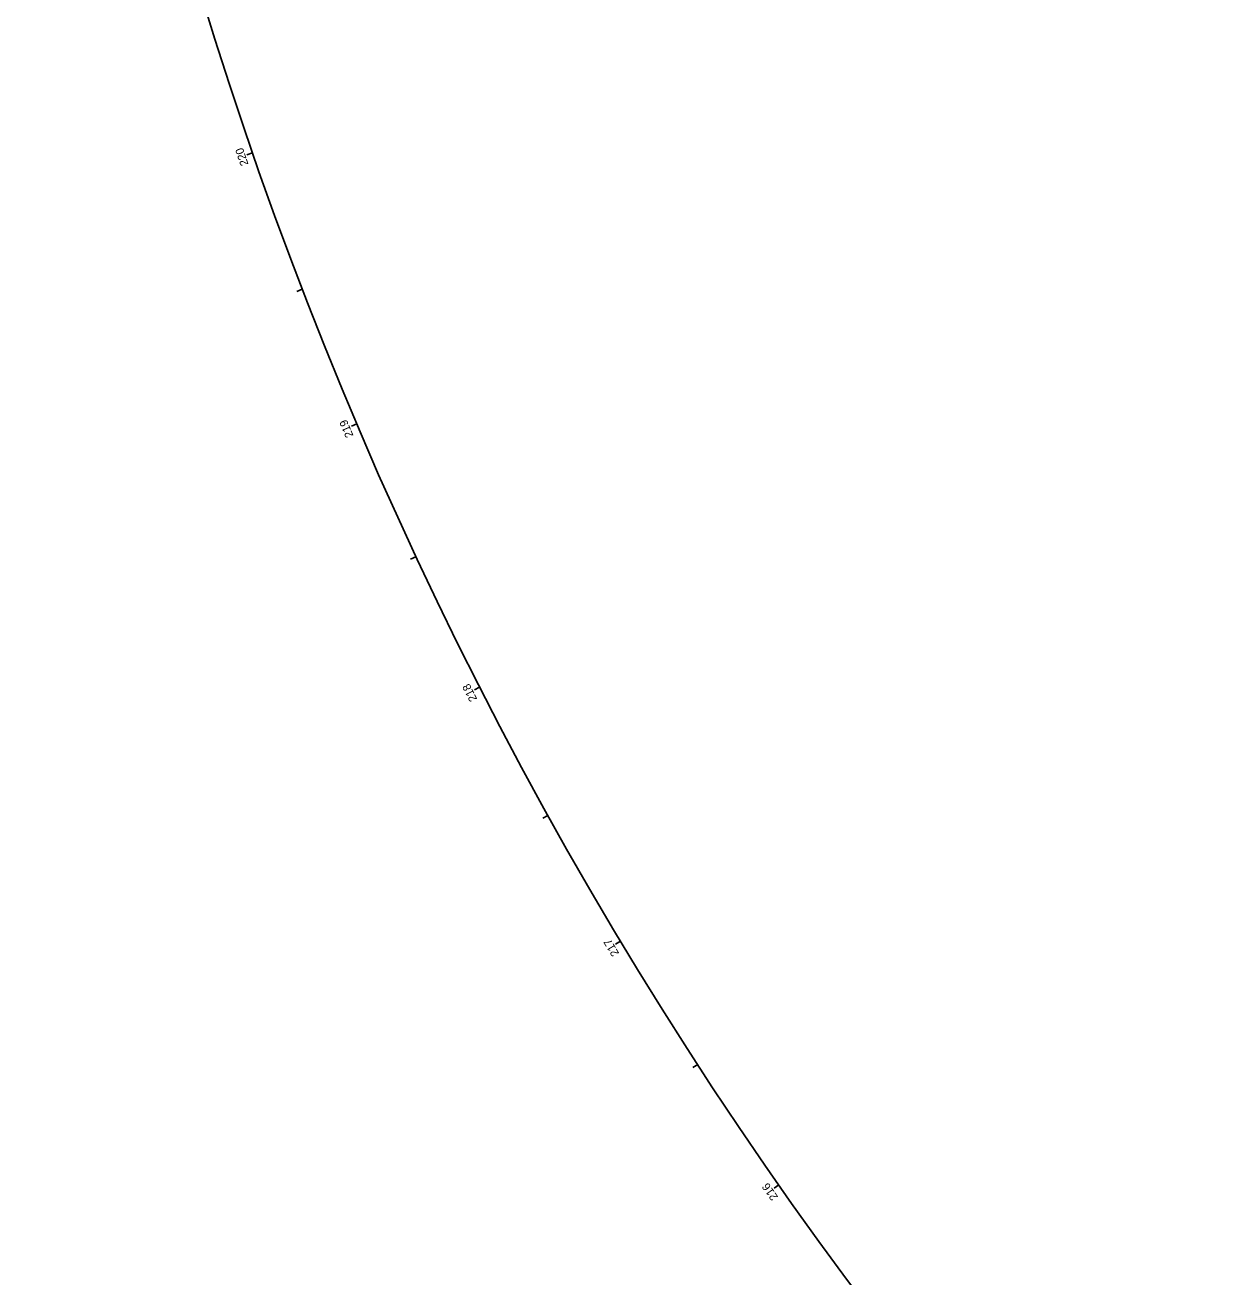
# Model space of a CAD drawing. Extents: x 1454426 to 1455277, y 587472 to 590476.
# Drawn here: x 1454431 to 1454844.3, y 587916.7 to 588347.4 of the extents above; entities that cross this region are included whole.
import ezdxf

# ---------------------------------------------------------------- set-up
doc = ezdxf.new("R2010")
doc.units = 0
for name, color, linetype in [('Default', 7, 'Continuous'), ('GT_Target_Soil_Boring', 7, 'Continuous'), ('PV_P_Saw_Cut_Line', 7, 'Continuous'), ('SC_Scratch1', 7, 'Continuous'), ('SC_Scratch2', 7, 'Continuous'), ('SC_Scratch3', 7, 'Continuous')]:
    doc.layers.add(name, color=color, linetype=linetype)

msp = doc.modelspace()

# ---------------------------------------------------------------- linework, layer by layer
at = {"layer": 'Default'}
for centre in [(1454509.27, 588303.48), (1454509.27, 588303.48), (1454509.27, 588303.48), (1454545.15, 588210.16), (1454545.15, 588210.16), (1454545.15, 588210.16), (1454587.45, 588119.57), (1454587.45, 588119.57), (1454587.45, 588119.57), (1454635.96, 588032.15), (1454635.96, 588032.15), (1454635.96, 588032.15), (1454690.46, 587948.33), (1454690.46, 587948.33), (1454690.46, 587948.33)]:
    msp.add_circle(centre, 0.0000833, dxfattribs=at)
at = {"layer": 'GT_Target_Soil_Boring'}
msp.add_arc((1455863.38, 588770.51), 1432.39, 161.3175, 244.97965, dxfattribs=at)
at = {"layer": 'PV_P_Saw_Cut_Line'}
msp.add_arc((1455863.38, 588770.51), 1432.39, 161.3175, 244.97965, dxfattribs=at)
at = {"layer": 'SC_Scratch1'}
for p, q in [((1454509.27, 588303.48), (1454507.38, 588302.83)), ((1454526.39, 588256.51), (1454524.53, 588255.79)), ((1454545.15, 588210.16), (1454543.31, 588209.38)), ((1454565.51, 588164.5), (1454563.69, 588163.65)), ((1454587.45, 588119.57), (1454585.66, 588118.66)), ((1454610.94, 588075.44), (1454609.19, 588074.47)), ((1454635.96, 588032.15), (1454634.25, 588031.12)), ((1454662.48, 587989.77), (1454660.8, 587988.68)), ((1454690.46, 587948.33), (1454688.82, 587947.18))]:
    msp.add_line(p, q, dxfattribs=at)
at = {"layer": 'SC_Scratch2'}
for p, q in [((1454509.27, 588303.48), (1454507.38, 588302.83)), ((1454526.39, 588256.51), (1454524.53, 588255.79)), ((1454545.15, 588210.16), (1454543.31, 588209.38)), ((1454565.51, 588164.5), (1454563.69, 588163.65)), ((1454587.45, 588119.57), (1454585.66, 588118.66)), ((1454610.94, 588075.44), (1454609.19, 588074.47)), ((1454635.96, 588032.15), (1454634.25, 588031.12)), ((1454662.48, 587989.77), (1454660.8, 587988.68)), ((1454690.46, 587948.33), (1454688.82, 587947.18))]:
    msp.add_line(p, q, dxfattribs=at)
at = {"layer": 'SC_Scratch3'}
for p, q in [((1454509.27, 588303.48), (1454507.38, 588302.83)), ((1454526.39, 588256.51), (1454524.53, 588255.79)), ((1454545.15, 588210.16), (1454543.31, 588209.38)), ((1454565.51, 588164.5), (1454563.69, 588163.65)), ((1454587.45, 588119.57), (1454585.66, 588118.66)), ((1454610.94, 588075.44), (1454609.19, 588074.47)), ((1454635.96, 588032.15), (1454634.25, 588031.12)), ((1454662.48, 587989.77), (1454660.8, 587988.68)), ((1454690.46, 587948.33), (1454688.82, 587947.18))]:
    msp.add_line(p, q, dxfattribs=at)

# ---------------------------------------------------------------- texts
at = {"layer": 'SC_Scratch1'}
for s, rotation, p in [('220', 109.0291, (1454507.93, 588299.55)), ('219', 113.0291, (1454544.07, 588206.17)), ('218', 117.0291, (1454586.67, 588115.49)), ('217', 121.0291, (1454635.54, 588028)), ('216', 125.0292, (1454690.26, 587944.18))]:
    msp.add_text(s, height=2.8, rotation=rotation, dxfattribs=at).set_placement(p)
at = {"layer": 'SC_Scratch2'}
for s, rotation, p in [('220', 109.0291, (1454507.93, 588299.55)), ('219', 113.0291, (1454544.07, 588206.17)), ('218', 117.0291, (1454586.67, 588115.49)), ('217', 121.0291, (1454635.54, 588028)), ('216', 125.0292, (1454690.26, 587944.18))]:
    msp.add_text(s, height=2.8, rotation=rotation, dxfattribs=at).set_placement(p)
at = {"layer": 'SC_Scratch3'}
for s, rotation, p in [('220', 109.0291, (1454507.93, 588299.55)), ('219', 113.0291, (1454544.07, 588206.17)), ('218', 117.0291, (1454586.67, 588115.49)), ('217', 121.0291, (1454635.54, 588028)), ('216', 125.0292, (1454690.26, 587944.18))]:
    msp.add_text(s, height=2.8, rotation=rotation, dxfattribs=at).set_placement(p)

doc.saveas('drawing.dxf')
